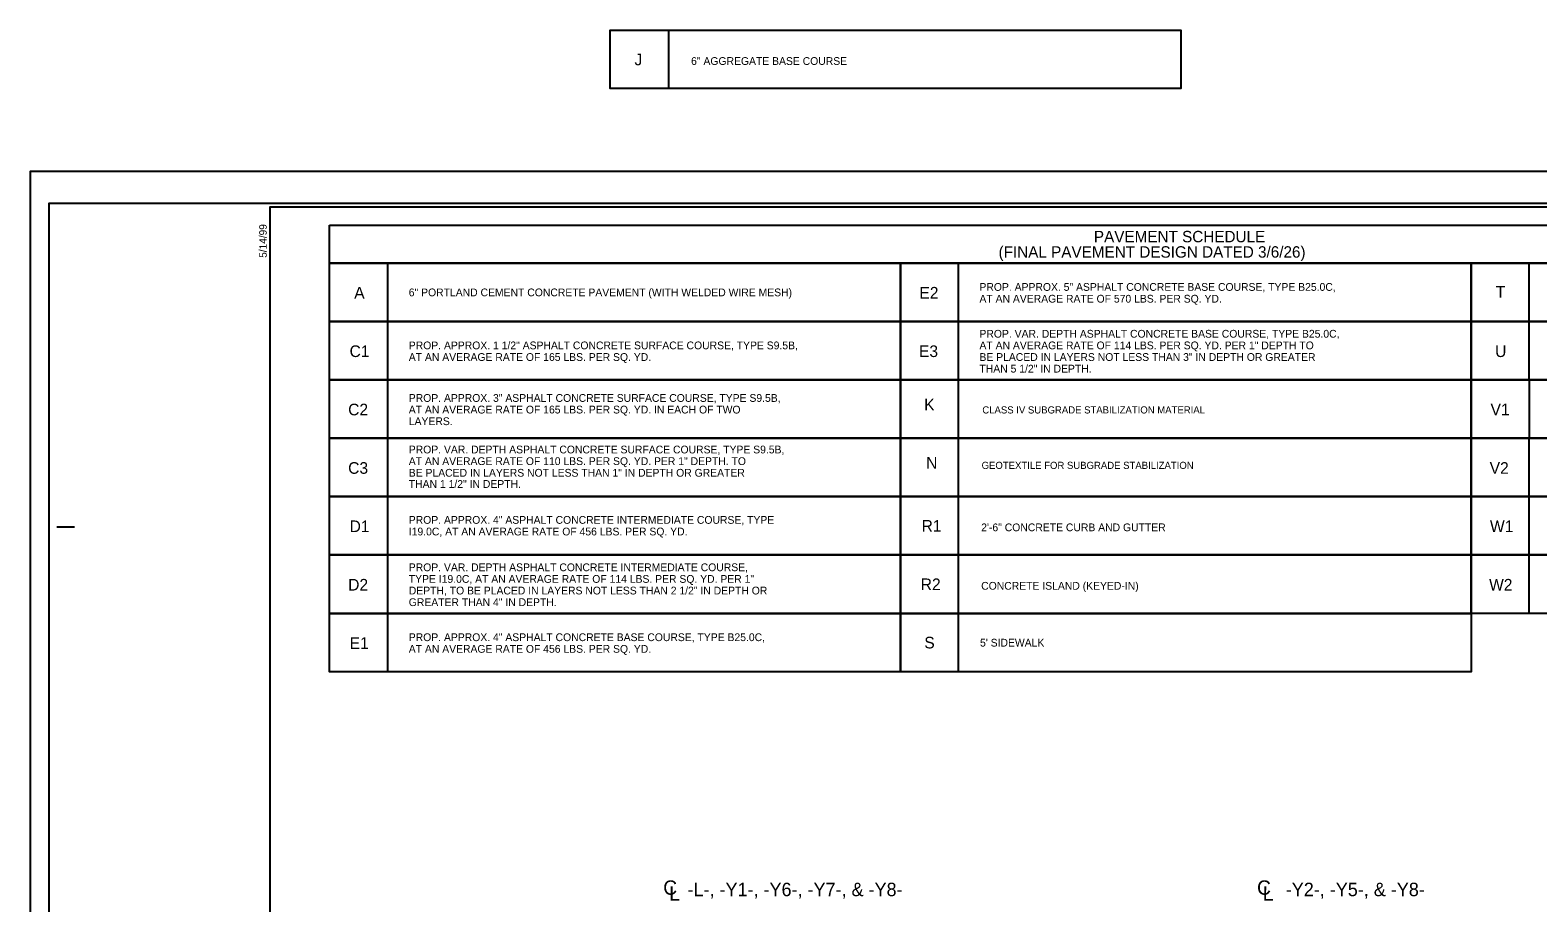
# Model space of a CAD drawing. Extents: x 1901670 to 1902225, y 193498 to 194278.
# Drawn here: x 1901965.8 to 1902070.8, y 194217.1 to 194277.8 of the extents above; entities that cross this region are included whole.
import ezdxf

# ---------------------------------------------------------------- set-up
doc = ezdxf.new("R2010")
doc.units = 0
for name, color, linetype in [('Old_Level_19', 7, 'Continuous'), ('Old_Level_2', 7, 'Continuous'), ('Old_Level_21', 7, 'Continuous'), ('Prop Lane Arrow CELL', 7, 'Continuous'), ('Prop Pavement Schedule Description CELL', 7, 'Continuous'), ('Sheet Border Standard 30in CELL', 7, 'Continuous'), ('Sheet Cutting Line CELL', 7, 'Continuous'), ('Sheet Plot Border Inside CELL', 7, 'Continuous'), ('Sheet Plot Border Outside CELL', 7, 'Continuous')]:
    doc.layers.add(name, color=color, linetype=linetype)

msp = doc.modelspace()

# ---------------------------------------------------------------- linework, layer by layer
at = {"layer": 'Old_Level_19'}
for points in [[(1902010.31, 194273.78), (1902006.24, 194273.78), (1902006.24, 194277.84), (1902045.98, 194277.84), (1902045.98, 194273.78), (1902010.31, 194273.78), (1902010.31, 194277.84)], [(1901990.76, 194257.56), (1901986.7, 194257.56), (1901986.7, 194261.62), (1902026.44, 194261.62), (1902026.44, 194257.56), (1901990.76, 194257.56), (1901990.76, 194261.62)], [(1902030.5, 194257.56), (1902026.44, 194257.56), (1902026.44, 194261.62), (1902066.18, 194261.62), (1902066.18, 194257.56), (1902030.5, 194257.56), (1902030.5, 194261.62)], [(1902070.24, 194257.56), (1902066.18, 194257.56), (1902066.18, 194261.62), (1902105.92, 194261.62), (1902105.92, 194257.56), (1902070.24, 194257.56), (1902070.24, 194261.62)], [(1901990.76, 194253.49), (1901986.7, 194253.49), (1901986.7, 194257.56), (1902026.44, 194257.56), (1902026.44, 194253.49), (1901990.76, 194253.49), (1901990.76, 194257.56)], [(1902030.5, 194253.49), (1902026.44, 194253.49), (1902026.44, 194257.56), (1902066.18, 194257.56), (1902066.18, 194253.49), (1902030.5, 194253.49), (1902030.5, 194257.56)], [(1902070.24, 194253.49), (1902066.18, 194253.49), (1902066.18, 194257.56), (1902105.92, 194257.56), (1902105.92, 194253.49), (1902070.24, 194253.49), (1902070.24, 194257.56)], [(1901990.76, 194249.43), (1901986.7, 194249.43), (1901986.7, 194253.49), (1902026.44, 194253.49), (1902026.44, 194249.43), (1901990.76, 194249.43), (1901990.76, 194253.49)], [(1902070.25, 194249.43), (1902066.18, 194249.43), (1902066.18, 194253.49), (1902105.92, 194253.49), (1902105.92, 194249.43), (1902070.25, 194249.43), (1902070.25, 194253.49)], [(1901990.76, 194245.36), (1901986.7, 194245.36), (1901986.7, 194249.43), (1902026.44, 194249.43), (1902026.44, 194245.36), (1901990.76, 194245.36), (1901990.76, 194249.43)], [(1902070.24, 194245.36), (1902066.18, 194245.36), (1902066.18, 194249.43), (1902105.92, 194249.43), (1902105.92, 194245.36), (1902070.24, 194245.36), (1902070.24, 194249.43)], [(1901990.76, 194241.3), (1901986.7, 194241.3), (1901986.7, 194245.36), (1902026.44, 194245.36), (1902026.44, 194241.3), (1901990.76, 194241.3), (1901990.76, 194245.36)], [(1902030.5, 194241.3), (1902026.44, 194241.3), (1902026.44, 194245.36), (1902066.18, 194245.36), (1902066.18, 194241.3), (1902030.5, 194241.3), (1902030.5, 194245.36)], [(1902070.24, 194241.3), (1902066.18, 194241.3), (1902066.18, 194245.36), (1902105.92, 194245.36), (1902105.92, 194241.3), (1902070.24, 194241.3), (1902070.24, 194245.36)], [(1901990.76, 194237.23), (1901986.7, 194237.23), (1901986.7, 194241.3), (1902026.44, 194241.3), (1902026.44, 194237.23), (1901990.76, 194237.23), (1901990.76, 194241.3)], [(1902030.5, 194237.23), (1902026.44, 194237.23), (1902026.44, 194241.3), (1902066.18, 194241.3), (1902066.18, 194237.23), (1902030.5, 194237.23), (1902030.5, 194241.3)], [(1902070.24, 194237.23), (1902066.18, 194237.23), (1902066.18, 194241.3), (1902105.92, 194241.3), (1902105.92, 194237.23), (1902070.24, 194237.23), (1902070.24, 194241.3)], [(1901990.76, 194233.17), (1901986.7, 194233.17), (1901986.7, 194237.23), (1902026.44, 194237.23), (1902026.44, 194233.17), (1901990.76, 194233.17), (1901990.76, 194237.23)], [(1902030.5, 194233.17), (1902026.44, 194233.17), (1902026.44, 194237.23), (1902066.18, 194237.23), (1902066.18, 194233.17), (1902030.5, 194233.17), (1902030.5, 194237.23)]]:
    msp.add_lwpolyline(points, dxfattribs=at)
at = {"layer": 'Prop Pavement Schedule Description CELL'}
msp.add_lwpolyline([(1901986.7, 194264.26), (1902105.91, 194264.26), (1902105.91, 194261.62), (1901986.7, 194261.62)], close=True, dxfattribs=at)
for points in [[(1902030.5, 194249.43), (1902026.44, 194249.43), (1902026.44, 194253.49), (1902066.18, 194253.49), (1902066.18, 194249.43), (1902030.5, 194249.43), (1902030.5, 194253.49)], [(1902030.5, 194245.36), (1902026.44, 194245.36), (1902026.44, 194249.43), (1902066.18, 194249.43), (1902066.18, 194245.36), (1902030.5, 194245.36), (1902030.5, 194249.43)]]:
    msp.add_lwpolyline(points, dxfattribs=at)
at = {"layer": 'Sheet Border Standard 30in CELL'}
for p, q in [((1901982.64, 194265.51), (1901982.64, 194265.51)), ((1901967.69, 194243.26), (1901968.94, 194243.26))]:
    msp.add_line(p, q, dxfattribs=at)
msp.add_lwpolyline([(1902132.54, 194265.51), (1901982.54, 194265.51), (1901982.54, 194160.51), (1902132.54, 194160.51)], close=True, dxfattribs=at)
at = {"layer": 'Sheet Cutting Line CELL'}
for p, q in [((1902134.24, 194268.01), (1901965.84, 194268.01)), ((1901965.84, 194268.01), (1901965.84, 194158.01))]:
    msp.add_line(p, q, dxfattribs=at)
at = {"layer": 'Sheet Plot Border Inside CELL'}
msp.add_lwpolyline([(1902133.79, 194265.77), (1901967.14, 194265.77), (1901967.14, 194160.26), (1902133.79, 194160.26)], close=True, dxfattribs=at)
at = {"layer": 'Sheet Plot Border Outside CELL'}
msp.add_lwpolyline([(1902134.24, 194268.01), (1901965.84, 194268.01), (1901965.84, 194158.01), (1902134.24, 194158.01)], close=True, dxfattribs=at)

# ---------------------------------------------------------------- texts
at = {"layer": 'Old_Level_2'}
for p in [(1902009.93, 194217.64), (1902051.28, 194217.64)]:
    msp.add_text('C', height=1, dxfattribs=at).set_placement(p)
for p in [(1902010.34, 194217.23), (1902051.68, 194217.23)]:
    msp.add_text('L', height=1, rotation=359.9469, dxfattribs=at).set_placement(p)
at = {"layer": 'Old_Level_21'}
for s, height, p in [('J', 0.811, (1902007.93, 194275.39)), ('6" AGGREGATE BASE COURSE', 0.5407, (1902011.87, 194275.42)), ('A', 0.811, (1901988.41, 194259.15)), ('6" PORTLAND CEMENT CONCRETE PAVEMENT (WITH WELDED WIRE MESH)', 0.5407, (1901992.21, 194259.31)), ('E2', 0.811, (1902027.77, 194259.15)), ('AT AN AVERAGE RATE OF 570 LBS. PER SQ. YD.', 0.5407, (1902031.95, 194258.87)), ('PROP. APPROX. 5" ASPHALT CONCRETE BASE COURSE, TYPE B25.0C,', 0.5407, (1902031.95, 194259.69)), ('T', 0.811, (1902067.9, 194259.21)), ('PROP. APPROX. 1 1/2" ASPHALT CONCRETE SURFACE COURSE, TYPE S9.5B,', 0.5407, (1901992.21, 194255.62)), ('AT AN AVERAGE RATE OF 114 LBS. PER SQ. YD. PER 1" DEPTH TO', 0.5407, (1902031.95, 194255.62)), ('PROP. VAR. DEPTH ASPHALT CONCRETE BASE COURSE, TYPE B25.0C,', 0.5407, (1902031.95, 194256.43)), ('C1', 0.811, (1901988.09, 194255.08)), ('AT AN AVERAGE RATE OF 165 LBS. PER SQ. YD.', 0.5407, (1901992.21, 194254.81)), ('E3', 0.811, (1902027.74, 194255.08)), ('BE PLACED IN LAYERS NOT LESS THAN 3" IN DEPTH OR GREATER', 0.5407, (1902031.95, 194254.81)), ('U', 0.811, (1902067.86, 194255.08)), ('THAN 5 1/2" IN DEPTH.', 0.5407, (1902031.95, 194254)), ('PROP. APPROX. 3" ASPHALT CONCRETE SURFACE COURSE, TYPE S9.5B,', 0.5407, (1901992.21, 194251.96)), ('C2', 0.811, (1901987.99, 194251.02)), ('AT AN AVERAGE RATE OF 165 LBS. PER SQ. YD. IN EACH OF TWO', 0.5407, (1901992.21, 194251.15)), ('LAYERS.', 0.541, (1901992.21, 194250.34)), ('V1', 0.811, (1902067.54, 194251.02)), ('PROP. VAR. DEPTH ASPHALT CONCRETE SURFACE COURSE, TYPE S9.5B,', 0.5407, (1901992.21, 194248.37)), ('C3', 0.811, (1901987.99, 194246.95)), ('AT AN AVERAGE RATE OF 110 LBS. PER SQ. YD. PER 1" DEPTH. TO', 0.5407, (1901992.21, 194247.56)), ('V2', 0.811, (1902067.48, 194246.95)), ('BE PLACED IN LAYERS NOT LESS THAN 1" IN DEPTH OR GREATER', 0.5407, (1901992.21, 194246.75)), ('THAN 1 1/2" IN DEPTH.', 0.5407, (1901992.21, 194245.97)), ('D1', 0.811, (1901988.09, 194242.89)), ('PROP. APPROX. 4" ASPHALT CONCRETE INTERMEDIATE COURSE, TYPE', 0.5407, (1901992.21, 194243.47)), ('R1', 0.811, (1902027.92, 194242.92)), ('W1', 0.811, (1902067.5, 194242.89)), ('I19.0C, AT AN AVERAGE RATE OF 456 LBS. PER SQ. YD.', 0.5407, (1901992.21, 194242.66)), ('2\'-6" CONCRETE CURB AND GUTTER', 0.5407, (1902032.07, 194242.95)), ('PROP. VAR. DEPTH ASPHALT CONCRETE INTERMEDIATE COURSE,', 0.5407, (1901992.21, 194240.17)), ('D2', 0.811, (1901987.99, 194238.82)), ('TYPE I19.0C, AT AN AVERAGE RATE OF 114 LBS. PER SQ. YD. PER 1" ', 0.5407, (1901992.21, 194239.36)), ('R2', 0.811, (1902027.86, 194238.85)), ('CONCRETE ISLAND (KEYED-IN)', 0.5407, (1902032.07, 194238.88)), ('W2', 0.811, (1902067.44, 194238.82)), ('GREATER THAN 4" IN DEPTH.', 0.5407, (1901992.21, 194237.74)), ('DEPTH, TO BE PLACED IN LAYERS NOT LESS THAN 2 1/2" IN DEPTH OR', 0.5407, (1901992.21, 194238.55)), ('E1', 0.811, (1901988.09, 194234.76)), ('PROP. APPROX. 4" ASPHALT CONCRETE BASE COURSE, TYPE B25.0C,', 0.5407, (1901992.21, 194235.3)), ('S', 0.811, (1902028.11, 194234.79)), ("5' SIDEWALK", 0.5407, (1902031.99, 194234.92)), ('AT AN AVERAGE RATE OF 456 LBS. PER SQ. YD.', 0.5407, (1901992.21, 194234.49))]:
    msp.add_text(s, height=height, dxfattribs=at).set_placement(p)
at = {"layer": 'Prop Lane Arrow CELL'}
for s, height, p in [('PAVEMENT SCHEDULE', 0.7947, (1902039.92, 194263.07)), ('(FINAL PAVEMENT DESIGN DATED 3/6/26)', 0.7947, (1902033.28, 194262)), ('-L-, -Y1-, -Y6-, -Y7-, & -Y8-', 0.9375, (1902011.62, 194217.54)), ('-Y2-, -Y5-, & -Y8-', 0.9375, (1902053.28, 194217.54))]:
    msp.add_text(s, height=height, dxfattribs=at).set_placement(p)
at = {"layer": 'Prop Pavement Schedule Description CELL'}
for s, height, p in [('K', 0.811, (1902028.1, 194251.36)), ('CLASS IV SUBGRADE STABILIZATION MATERIAL', 0.4968, (1902032.15, 194251.15)), ('N', 0.811, (1902028.24, 194247.3)), ('GEOTEXTILE FOR SUBGRADE STABILIZATION', 0.4968, (1902032.1, 194247.29))]:
    msp.add_text(s, height=height, dxfattribs=at).set_placement(p)
at = {"layer": 'Sheet Border Standard 30in CELL'}
msp.add_text('5/14/99', height=0.525, rotation=90, dxfattribs=at).set_placement((1901982.32, 194261.99))

doc.saveas('drawing.dxf')
